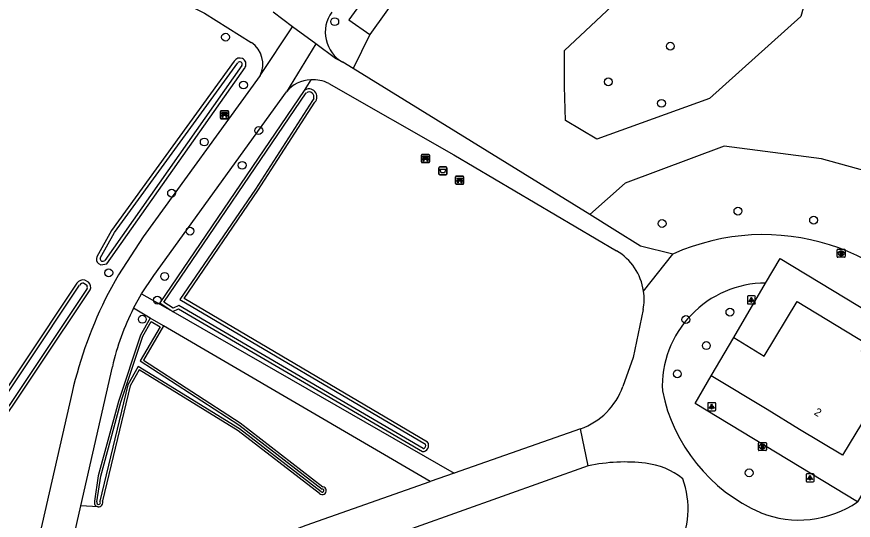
# Model space of a CAD drawing. Extents: x 157154 to 159278, y 385000 to 386650.
# Drawn here: x 158883.5 to 158988, y 385275.4 to 385338.3 of the extents above; entities that cross this region are included whole.
import ezdxf

# ---------------------------------------------------------------- set-up
doc = ezdxf.new("R2010")
doc.units = 0
for name, color, linetype in [('IMGEO_Afvalbak', 7, 'Continuous'), ('IMGEO_Bank', 7, 'Continuous'), ('IMGEO_Boom', 7, 'Continuous'), ('IMGEO_Gemengd_bos', 7, 'Continuous'), ('IMGEO_Grasland_overig', 7, 'Continuous'), ('IMGEO_Groenvoorziening', 7, 'Continuous'), ('IMGEO_Lichtpunt', 7, 'Continuous'), ('IMGEO_Pand', 7, 'Continuous'), ('IMGEO_Pand_nummerreeks', 7, 'Continuous'), ('IMGEO_Rioolput', 7, 'Continuous'), ('IMGEO_Voetpad_halfverhard', 7, 'Continuous'), ('IMGEO_Voetpad_onverhard', 7, 'Continuous'), ('IMGEO_Waterloop', 7, 'Continuous')]:
    doc.layers.add(name, color=color, linetype=linetype)

msp = doc.modelspace()

# ---------------------------------------------------------------- linework, layer by layer
at = {"layer": 'IMGEO_Afvalbak'}
for p, q in [((158936.23, 385318.65), (158936.23, 385319.45)), ((158936.23, 385319.45), (158936.23, 385318.65)), ((158936.33, 385319.55), (158937.12, 385319.55)), ((158937.12, 385319.55), (158936.33, 385319.55)), ((158937.22, 385319.45), (158937.22, 385318.65)), ((158937.22, 385318.65), (158937.22, 385319.45)), ((158937.12, 385318.55), (158936.33, 385318.55)), ((158936.33, 385318.55), (158937.12, 385318.55))]:
    msp.add_line(p, q, dxfattribs=at)
msp.add_lwpolyline([(158936.37, 385319.27), (158937.07, 385319.27), (158936.93, 385318.79), (158936.52, 385318.79), (158936.37, 385319.27)], dxfattribs=at)
for centre, start, end in [((158936.33, 385319.45), 90, 180), ((158936.33, 385319.45), 90, 180), ((158937.12, 385319.45), 0, 90), ((158937.12, 385319.45), 360, 90), ((158936.33, 385318.65), 180, 270), ((158936.33, 385318.65), 180, 270), ((158937.12, 385318.65), 270, 0), ((158937.12, 385318.65), 270, 0)]:
    msp.add_arc(centre, 0.1, start, end, dxfattribs=at)
at = {"layer": 'IMGEO_Bank'}
for p, q in [((158908.93, 385325.64), (158908.93, 385326.48)), ((158908.93, 385326.48), (158908.93, 385325.64)), ((158909.01, 385326.56), (158909.85, 385326.56)), ((158909.85, 385326.56), (158909.01, 385326.56)), ((158909.24, 385326.07), (158909.24, 385326.17)), ((158909.57, 385326.18), (158909.29, 385326.18)), ((158909.29, 385326.17), (158909.29, 385326.07)), ((158909.29, 385326.06), (158909.57, 385326.06)), ((158909.58, 385326.07), (158909.58, 385326.17)), ((158909.62, 385326.17), (158909.62, 385326.07)), ((158909.93, 385326.49), (158909.93, 385325.65)), ((158909.93, 385325.65), (158909.93, 385326.49)), ((158909.86, 385325.56), (158909.02, 385325.56)), ((158909.02, 385325.56), (158909.86, 385325.56)), ((158909.63, 385325.96), (158909.24, 385325.96)), ((158934.04, 385320.16), (158934.04, 385321.01)), ((158934.04, 385321.01), (158934.04, 385320.16)), ((158934.11, 385321.09), (158934.95, 385321.09)), ((158934.95, 385321.09), (158934.11, 385321.09)), ((158935.04, 385321.02), (158935.04, 385320.17)), ((158935.04, 385320.17), (158935.04, 385321.02)), ((158934.96, 385320.09), (158934.12, 385320.09)), ((158934.12, 385320.09), (158934.96, 385320.09)), ((158934.73, 385320.49), (158934.34, 385320.49)), ((158934.35, 385320.6), (158934.35, 385320.7)), ((158934.39, 385320.7), (158934.39, 385320.6)), ((158934.68, 385320.71), (158934.4, 385320.71)), ((158934.4, 385320.59), (158934.68, 385320.59)), ((158934.68, 385320.6), (158934.68, 385320.7)), ((158934.73, 385320.7), (158934.73, 385320.6)), ((158938.31, 385317.46), (158938.31, 385318.3)), ((158938.31, 385318.3), (158938.31, 385317.46)), ((158938.39, 385318.38), (158939.23, 385318.38)), ((158939.23, 385318.38), (158938.39, 385318.38)), ((158938.62, 385317.89), (158938.62, 385318)), ((158939.01, 385317.78), (158938.62, 385317.78)), ((158938.66, 385318), (158938.66, 385317.89)), ((158938.95, 385318), (158938.67, 385318)), ((158938.67, 385317.89), (158938.95, 385317.89)), ((158938.96, 385317.89), (158938.96, 385318)), ((158939, 385318), (158939, 385317.89)), ((158939.31, 385318.31), (158939.31, 385317.47)), ((158939.31, 385317.47), (158939.31, 385318.31)), ((158939.24, 385317.39), (158938.4, 385317.39)), ((158938.4, 385317.39), (158939.24, 385317.39))]:
    msp.add_line(p, q, dxfattribs=at)
for points in [[(158909.18, 385325.96), (158909.04, 385325.96), (158909.15, 385326.06), (158909.24, 385326.06)], [(158909.24, 385326.18), (158909.15, 385326.18), (158909.15, 385326.34), (158909.71, 385326.34), (158909.71, 385326.18), (158909.63, 385326.18)], [(158909.63, 385326.06), (158909.71, 385326.06), (158909.83, 385325.96), (158909.69, 385325.96)], [(158909.23, 385325.95), (158909.23, 385325.74), (158909.19, 385325.74), (158909.19, 385325.95)], [(158909.68, 385325.95), (158909.68, 385325.74), (158909.64, 385325.74), (158909.64, 385325.95)], [(158934.34, 385320.71), (158934.25, 385320.71), (158934.25, 385320.87), (158934.82, 385320.87), (158934.82, 385320.71), (158934.73, 385320.71)], [(158934.28, 385320.49), (158934.14, 385320.49), (158934.25, 385320.59), (158934.34, 385320.59)], [(158934.33, 385320.48), (158934.33, 385320.27), (158934.29, 385320.27), (158934.29, 385320.48)], [(158934.73, 385320.59), (158934.82, 385320.59), (158934.93, 385320.49), (158934.79, 385320.49)], [(158934.78, 385320.48), (158934.78, 385320.27), (158934.74, 385320.27), (158934.74, 385320.48)], [(158938.56, 385317.78), (158938.42, 385317.78), (158938.53, 385317.89), (158938.61, 385317.89)], [(158938.61, 385318), (158938.53, 385318), (158938.53, 385318.16), (158939.09, 385318.16), (158939.09, 385318), (158939.01, 385318)], [(158938.61, 385317.78), (158938.61, 385317.57), (158938.57, 385317.57), (158938.57, 385317.78)], [(158939.01, 385317.89), (158939.09, 385317.89), (158939.2, 385317.78), (158939.07, 385317.78)], [(158939.06, 385317.78), (158939.06, 385317.57), (158939.02, 385317.57), (158939.02, 385317.78)]]:
    msp.add_lwpolyline(points, dxfattribs=at)
for centre, radius, start, end in [((158909.01, 385326.48), 0.0779, 92.4484, 184.2845), ((158909.01, 385326.48), 0.0779, 92.4484, 184.2845), ((158909.24, 385326.17), 0.00671, 2.8957, 87.1043), ((158909.24, 385326.07), 0.00671, 272.8957, 357.1043), ((158909.29, 385326.17), 0.00671, 92.8957, 177.1043), ((158909.29, 385326.07), 0.00671, 182.8957, 267.1043), ((158909.57, 385326.17), 0.00671, 2.8957, 87.1043), ((158909.57, 385326.07), 0.00671, 272.8957, 357.1043), ((158909.63, 385326.17), 0.00671, 92.8957, 177.1043), ((158909.63, 385326.07), 0.00671, 182.8957, 267.1043), ((158909.85, 385326.48), 0.0779, 2.4484, 94.2845), ((158909.85, 385326.48), 0.0779, 2.4484, 94.2845), ((158909.01, 385325.64), 0.0779, 182.4484, 274.2845), ((158909.01, 385325.64), 0.0779, 182.4484, 274.2845), ((158909.18, 385325.95), 0.00671, 2.8957, 87.1043), ((158909.24, 385325.95), 0.00671, 92.8957, 177.1043), ((158909.63, 385325.95), 0.00671, 2.8957, 87.1043), ((158909.69, 385325.95), 0.00671, 92.8957, 177.1043), ((158909.85, 385325.64), 0.0779, 272.4484, 4.2845), ((158909.85, 385325.64), 0.0779, 272.4484, 4.2845), ((158934.11, 385321.01), 0.0779, 92.4484, 184.2845), ((158934.11, 385321.01), 0.0779, 92.4484, 184.2845), ((158934.96, 385321.01), 0.0779, 2.4484, 94.2845), ((158934.96, 385321.01), 0.0779, 2.4484, 94.2845), ((158934.11, 385320.17), 0.0779, 182.4484, 274.2845), ((158934.11, 385320.17), 0.0779, 182.4484, 274.2845), ((158934.28, 385320.48), 0.00671, 2.8957, 87.1043), ((158934.34, 385320.48), 0.00671, 92.8957, 177.1043), ((158934.34, 385320.7), 0.00671, 2.8957, 87.1043), ((158934.34, 385320.6), 0.00671, 272.8957, 357.1043), ((158934.4, 385320.7), 0.00671, 92.8957, 177.1043), ((158934.4, 385320.6), 0.00671, 182.8957, 267.1043), ((158934.68, 385320.7), 0.00671, 2.8957, 87.1043), ((158934.68, 385320.6), 0.00671, 272.8957, 357.1043), ((158934.73, 385320.7), 0.00671, 92.8957, 177.1043), ((158934.73, 385320.6), 0.00671, 182.8957, 267.1043), ((158934.73, 385320.48), 0.00671, 2.8957, 87.1043), ((158934.79, 385320.48), 0.00671, 92.8957, 177.1043), ((158934.96, 385320.17), 0.0779, 272.4484, 4.2845), ((158934.96, 385320.17), 0.0779, 272.4484, 4.2845), ((158938.39, 385318.31), 0.0779, 92.4484, 184.2845), ((158938.39, 385318.31), 0.0779, 92.4484, 184.2845), ((158938.56, 385317.78), 0.00671, 2.8957, 87.1043), ((158938.61, 385318), 0.00671, 2.8957, 87.1043), ((158938.61, 385317.89), 0.00671, 272.8957, 357.1043), ((158938.62, 385317.78), 0.00671, 92.8957, 177.1043), ((158938.67, 385318), 0.00671, 92.8957, 177.1043), ((158938.67, 385317.89), 0.00671, 182.8957, 267.1043), ((158938.95, 385318), 0.00671, 2.8957, 87.1043), ((158938.95, 385317.89), 0.00671, 272.8957, 357.1043), ((158939.01, 385318), 0.00671, 92.8957, 177.1043), ((158939.01, 385317.89), 0.00671, 182.8957, 267.1043), ((158939.01, 385317.78), 0.00671, 2.8957, 87.1043), ((158939.07, 385317.78), 0.00671, 92.8957, 177.1043), ((158939.23, 385318.31), 0.0779, 2.4484, 94.2845), ((158939.23, 385318.31), 0.0779, 2.4484, 94.2845), ((158938.39, 385317.46), 0.0779, 182.4484, 274.2845), ((158938.39, 385317.46), 0.0779, 182.4484, 274.2845), ((158939.23, 385317.46), 0.0779, 272.4484, 4.2845), ((158939.23, 385317.46), 0.0779, 272.4484, 4.2845)]:
    msp.add_arc(centre, radius, start, end, dxfattribs=at)
at = {"layer": 'IMGEO_Boom'}
for centre in [(158923.21, 385337.7), (158909.57, 385335.76), (158965.13, 385334.63), (158911.81, 385329.78), (158957.39, 385330.18), (158964.03, 385327.49), (158913.72, 385324.09), (158906.91, 385322.66), (158911.65, 385319.75), (158902.83, 385316.27), (158973.58, 385314.02), (158964.11, 385312.47), (158983.03, 385312.89), (158905.13, 385311.52), (158894.98, 385306.31), (158901.96, 385305.86), (158901.04, 385302.9), (158899.18, 385300.51), (158967.08, 385300.47), (158972.58, 385301.4), (158969.63, 385297.22), (158966.01, 385293.68), (158974.98, 385281.31)]:
    msp.add_circle(centre, 0.489, dxfattribs=at)
at = {"layer": 'IMGEO_Gemengd_bos'}
for points in [[(158910.66, 385332.76), (158895.31, 385311.6), (158893.47, 385308.32)], [(158893.7, 385307.47), (158893.98, 385307.32), (158894.74, 385307.43), (158912.03, 385331.99)], [(158920.21, 385330.44), (158919.39, 385329.08)], [(158934.8, 385285.16), (158904.38, 385303.09), (158913.61, 385316.58), (158920.73, 385327.63)], [(158892.46, 385305.15), (158892.01, 385305.41)], [(158891, 385305), (158877.2, 385284.35), (158872.07, 385275.9)], [(158873.01, 385274.81), (158892.67, 385304.19)], [(158902.99, 385301.47), (158903.71, 385301.8), (158934.16, 385283.97)], [(158902.99, 385301.47), (158938.12, 385281.28)], [(158901.81, 385299.67), (158899.33, 385295.41), (158911.39, 385287.56), (158921.73, 385279.58)], [(158935.13, 385280.23), (158901.81, 385299.67)], [(158921.32, 385278.72), (158911.14, 385286.57), (158898.77, 385294.19), (158897.67, 385292.19), (158894.2, 385277.83)], [(158893.64, 385277.08), (158891.49, 385277.2)]]:
    msp.add_lwpolyline(points, dxfattribs=at)
for centre, radius, start, end in [((158911.34, 385332.37), 0.785, 65.1242, 150.1059), ((158911.34, 385332.37), 0.784, 331.4126, 65.077), ((158920, 385328.3), 0.991, 317.4306, 127.7685), ((158894.24, 385308.07), 0.81, 161.9369, 227.7161), ((158891.79, 385304.5), 0.937, 76.4308, 147.1916), ((158891.79, 385304.49), 0.938, 340.9432, 44.1903), ((158934.19, 385284.72), 0.755, 268.2883, 35.3972), ((158921.66, 385279.09), 0.5, 227.2488, 81.9846), ((158893.69, 385277.62), 0.545, 264.4615, 22.0934)]:
    msp.add_arc(centre, radius, start, end, dxfattribs=at)
at = {"layer": 'IMGEO_Grasland_overig'}
for points in [[(158899.08, 385303.7), (158902.99, 385301.47)], [(158900.16, 385300.66), (158898.07, 385301.88)], [(158901.81, 385299.67), (158900.16, 385300.66)]]:
    msp.add_lwpolyline(points, dxfattribs=at)
at = {"layer": 'IMGEO_Groenvoorziening'}
for points in [[(158981.42, 385338.35), (158970.02, 385328.1), (158955.96, 385323.03), (158952.04, 385325.34), (158951.93, 385329.6), (158951.93, 385334.09), (158963.79, 385345.27), (158969.32, 385358.05), (158966.33, 385370.26), (158969.67, 385375.22), (158974.97, 385377.17), (158982, 385373.26), (158985.45, 385352.75), (158981.42, 385338.35)], [(158927.58, 385336.09), (158925.53, 385331.86)], [(158919.39, 385329.08), (158901.35, 385302.54), (158902.99, 385301.47)], [(159015.68, 385286.71), (159007.51, 385302.78), (159003.96, 385308.59), (158993.24, 385318.03), (158984.03, 385320.57), (158971.87, 385322.12), (158959.49, 385317.52), (158955.07, 385313.58)], [(158973.05, 385298.22), (158977.04, 385305.03)], [(158900.16, 385300.66), (158898.96, 385298.51), (158896.19, 385290.24), (158893.67, 385280.95), (158893.21, 385277.78)], [(158988.52, 385277.69), (158968.22, 385289.99), (158970.25, 385293.44)]]:
    msp.add_lwpolyline(points, dxfattribs=at)
msp.add_arc((158893.71, 385277.61), 0.533, 161.1695, 262.31, dxfattribs=at)
at = {"layer": 'IMGEO_Lichtpunt'}
for p, q in [((158974.76, 385303.32), (158974.76, 385302.51)), ((158974.76, 385303.32), (158974.76, 385302.51)), ((158975.66, 385303.42), (158974.85, 385303.42)), ((158975.66, 385303.42), (158974.85, 385303.42)), ((158975.75, 385302.51), (158975.75, 385303.32)), ((158975.75, 385302.51), (158975.75, 385303.32)), ((158974.85, 385302.42), (158975.66, 385302.42)), ((158974.85, 385302.42), (158975.66, 385302.42)), ((158969.81, 385289.98), (158969.81, 385289.18)), ((158969.81, 385289.98), (158969.81, 385289.18)), ((158970.71, 385290.08), (158969.9, 385290.08)), ((158970.71, 385290.08), (158969.9, 385290.08)), ((158970.8, 385289.18), (158970.8, 385289.98)), ((158970.8, 385289.18), (158970.8, 385289.98)), ((158969.9, 385289.08), (158970.71, 385289.08)), ((158969.9, 385289.08), (158970.71, 385289.08)), ((158982.99, 385281.19), (158982.18, 385281.19)), ((158982.99, 385281.19), (158982.18, 385281.19)), ((158982.09, 385281.1), (158982.09, 385280.29)), ((158982.09, 385281.1), (158982.09, 385280.29)), ((158982.18, 385280.19), (158982.99, 385280.19)), ((158982.18, 385280.19), (158982.99, 385280.19)), ((158983.09, 385280.29), (158983.09, 385281.1)), ((158983.09, 385280.29), (158983.09, 385281.1))]:
    msp.add_line(p, q, dxfattribs=at)
for points in [[(158975.13, 385302.98), (158975.17, 385302.96), (158974.98, 385302.69), (158974.94, 385302.72), (158975.13, 385302.98)], [(158975.23, 385302.94), (158975.28, 385302.94), (158975.28, 385302.61), (158975.23, 385302.61), (158975.23, 385302.94)], [(158975.34, 385302.96), (158975.38, 385302.98), (158975.57, 385302.72), (158975.53, 385302.69), (158975.34, 385302.96)], [(158970.18, 385289.65), (158970.22, 385289.62), (158970.03, 385289.36), (158969.99, 385289.38), (158970.18, 385289.65)], [(158970.28, 385289.6), (158970.33, 385289.6), (158970.33, 385289.28), (158970.28, 385289.28), (158970.28, 385289.6)], [(158970.39, 385289.62), (158970.43, 385289.65), (158970.62, 385289.38), (158970.58, 385289.36), (158970.39, 385289.62)], [(158982.46, 385280.76), (158982.5, 385280.73), (158982.31, 385280.47), (158982.28, 385280.5), (158982.46, 385280.76)], [(158982.56, 385280.71), (158982.61, 385280.71), (158982.61, 385280.39), (158982.56, 385280.39), (158982.56, 385280.71)], [(158982.67, 385280.73), (158982.71, 385280.76), (158982.9, 385280.5), (158982.86, 385280.47), (158982.67, 385280.73)]]:
    msp.add_lwpolyline(points, dxfattribs=at)
for centre in [(158975.26, 385303.12), (158970.31, 385289.78), (158982.59, 385280.89)]:
    msp.add_circle(centre, 0.0994, dxfattribs=at)
for centre, start, end in [((158974.85, 385303.32), 90, 180), ((158974.85, 385303.32), 90, 180), ((158975.66, 385303.32), 0, 90), ((158975.66, 385303.32), 0, 90), ((158974.85, 385302.51), 180, 270), ((158974.85, 385302.51), 180, 270), ((158975.66, 385302.51), 270, 0), ((158975.66, 385302.51), 270, 360), ((158969.9, 385289.98), 90, 180), ((158969.9, 385289.98), 90, 180), ((158970.71, 385289.98), 0, 90), ((158970.71, 385289.98), 0, 90), ((158969.9, 385289.18), 180, 270), ((158969.9, 385289.18), 180, 270), ((158970.71, 385289.18), 270, 0), ((158970.71, 385289.18), 270, 360), ((158982.18, 385281.1), 90, 180), ((158982.18, 385281.1), 90, 180), ((158982.99, 385281.1), 0, 90), ((158982.99, 385281.1), 0, 90), ((158982.18, 385280.29), 180, 270), ((158982.18, 385280.29), 180, 270), ((158982.99, 385280.29), 270, 0), ((158982.99, 385280.29), 270, 360)]:
    msp.add_arc(centre, 0.0946, start, end, dxfattribs=at)
at = {"layer": 'IMGEO_Pand'}
for points in [[(158973.05, 385298.22), (158976.86, 385295.91), (158980.99, 385302.72), (158989.54, 385297.54), (158988.97, 385296.6), (158993.07, 385294.12), (158986.64, 385283.51), (158981.29, 385286.74), (158977.23, 385289.21), (158970.25, 385293.44)], [(158970.25, 385293.44), (158973.05, 385298.22)]]:
    msp.add_lwpolyline(points, dxfattribs=at)
at = {"layer": 'IMGEO_Rioolput'}
for p, q in [((158985.98, 385308.33), (158985.98, 385309.18)), ((158986.05, 385309.25), (158986.9, 385309.25)), ((158986.49, 385308.47), (158986.46, 385308.47)), ((158986.47, 385309.03), (158986.49, 385309.03)), ((158986.98, 385309.18), (158986.98, 385308.33)), ((158986.9, 385308.25), (158986.05, 385308.25)), ((158976.13, 385284.17), (158976.13, 385285.02)), ((158976.21, 385285.1), (158977.06, 385285.1)), ((158976.62, 385284.88), (158976.65, 385284.88)), ((158976.64, 385284.32), (158976.62, 385284.32)), ((158977.13, 385285.02), (158977.13, 385284.17)), ((158977.06, 385284.1), (158976.21, 385284.1))]:
    msp.add_line(p, q, dxfattribs=at)
for points in [[(158985.98, 385308.33), (158985.98, 385309.18)], [(158986.05, 385309.25), (158986.9, 385309.25)], [(158986.57, 385308.95), (158986.31, 385308.95), (158986.31, 385308.55)], [(158986.31, 385308.55), (158986.44, 385308.55), (158986.44, 385308.72), (158986.45, 385308.72)], [(158986.49, 385308.87), (158986.44, 385308.87), (158986.44, 385308.79)], [(158986.44, 385308.79), (158986.49, 385308.79)], [(158986.5, 385308.69), (158986.57, 385308.55), (158986.71, 385308.55), (158986.64, 385308.68)], [(158986.98, 385309.18), (158986.98, 385308.33)], [(158986.9, 385308.25), (158986.05, 385308.25)], [(158976.13, 385284.17), (158976.13, 385285.02)], [(158976.21, 385285.1), (158977.06, 385285.1)], [(158976.72, 385284.8), (158976.47, 385284.8), (158976.47, 385284.4)], [(158976.47, 385284.4), (158976.59, 385284.4), (158976.59, 385284.56), (158976.61, 385284.56)], [(158976.65, 385284.72), (158976.59, 385284.72), (158976.59, 385284.64)], [(158976.59, 385284.64), (158976.65, 385284.64)], [(158976.65, 385284.53), (158976.72, 385284.4), (158976.86, 385284.4), (158976.8, 385284.52)], [(158977.13, 385285.02), (158977.13, 385284.17)], [(158977.06, 385284.1), (158976.21, 385284.1)]]:
    msp.add_lwpolyline(points, dxfattribs=at)
for centre, radius, start, end in [((158986.05, 385309.18), 0.0765, 91.552, 178.448), ((158986.05, 385309.18), 0.0765, 91.552, 178.448), ((158986.05, 385308.33), 0.0765, 181.552, 268.448), ((158986.05, 385308.33), 0.0765, 181.552, 268.448), ((158986.45, 385308.66), 0.0533, 26.0293, 88.6989), ((158986.5, 385308.78), 0.0964, 77.0061, 93.1865), ((158986.47, 385308.98), 0.19, 274.7715, 282.9687), ((158986.51, 385308.83), 0.0378, 276.6634, 79.6772), ((158986.57, 385308.84), 0.109, 350.3612, 89.416), ((158986.56, 385308.84), 0.112, 277.5842, 350.9817), ((158986.55, 385308.63), 0.108, 29.5134, 73.7905), ((158986.9, 385309.18), 0.0765, 1.552, 88.448), ((158986.9, 385309.18), 0.0765, 1.552, 88.448), ((158986.9, 385308.33), 0.0765, 271.552, 358.448), ((158986.9, 385308.33), 0.0765, 271.552, 358.448), ((158976.21, 385285.02), 0.0765, 91.552, 178.448), ((158976.21, 385285.02), 0.0765, 91.552, 178.448), ((158976.6, 385284.51), 0.0533, 26.0293, 88.6989), ((158976.65, 385284.62), 0.0964, 77.0061, 93.1865), ((158976.63, 385284.83), 0.19, 274.7715, 282.9687), ((158976.67, 385284.68), 0.0378, 276.6634, 79.6772), ((158976.72, 385284.69), 0.109, 350.3612, 89.416), ((158976.72, 385284.69), 0.112, 277.5842, 350.9817), ((158976.7, 385284.47), 0.108, 29.5134, 73.7905), ((158977.06, 385285.02), 0.0765, 1.552, 88.448), ((158977.06, 385285.02), 0.0765, 1.552, 88.448), ((158976.21, 385284.17), 0.0765, 181.552, 268.448), ((158976.21, 385284.17), 0.0765, 181.552, 268.448), ((158977.06, 385284.17), 0.0765, 271.552, 358.448), ((158977.06, 385284.17), 0.0765, 271.552, 358.448)]:
    msp.add_arc(centre, radius, start, end, dxfattribs=at)
for centre, major_axis, ratio, start_param, end_param in [((158986.46, 385308.75), (-0.387, 0.002), 0.722429, 4.712389, 7.853982), ((158986.49, 385308.75), (-0.39, 0.002), 0.717154, 1.570796, 4.712389), ((158976.62, 385284.6), (-0.387, 0.002), 0.722429, 4.712389, 7.853982), ((158976.64, 385284.6), (-0.39, 0.002), 0.717154, 1.570796, 4.712389)]:
    msp.add_ellipse(centre, major_axis=major_axis, ratio=ratio, start_param=start_param, end_param=end_param, dxfattribs=at)
at = {"layer": 'IMGEO_Voetpad_halfverhard'}
for points in [[(158882.86, 385351.03), (158906.93, 385338.75), (158912.79, 385335.08)], [(158917.95, 385337.07), (158915.52, 385338.87)], [(158913.9, 385330.95), (158917.95, 385337.07)], [(158920.85, 385334.93), (158917.95, 385337.07)], [(158920.85, 385334.93), (158917.17, 385328.94)], [(158924.21, 385332.62), (158923.31, 385333.11), (158920.85, 385334.93)], [(158925.53, 385331.86), (158924.21, 385332.62)], [(158955.07, 385313.58), (158925.53, 385331.86)], [(158913.9, 385330.95), (158899.26, 385310.8), (158896.19, 385306.08), (158894.91, 385303.73)], [(158922.46, 385329.98), (158938.1, 385321.05), (158958.41, 385309.07)], [(158899.08, 385303.7), (158900.59, 385305.99), (158917.17, 385328.94)], [(158965.46, 385308.66), (158961.42, 385309.66), (158958.2, 385311.65), (158955.07, 385313.58)], [(158961.79, 385304.03), (158965.46, 385308.66)], [(158977.04, 385305.03), (158978.84, 385308.11), (158993.5, 385299.22), (158992.43, 385297.45), (158998.32, 385293.88), (158988.52, 385277.69)], [(158898.07, 385301.88), (158899.08, 385303.7)], [(158961.74, 385301.72), (158960.48, 385295.72), (158959.21, 385292.11)], [(158891.49, 385277.2), (158895.43, 385294.58)], [(158890.4, 385291.39), (158884.1, 385263.88)], [(158953.92, 385286.82), (158938.12, 385281.28)], [(158954.89, 385282.17), (158953.92, 385286.82)], [(158954.89, 385282.17), (158890.39, 385259.19)], [(158938.12, 385281.28), (158935.13, 385280.23)], [(158890.05, 385263.4), (158919.62, 385274.79), (158935.13, 385280.23)], [(158888.68, 385264.85), (158891.49, 385277.2)]]:
    msp.add_lwpolyline(points, dxfattribs=at)
for centre, radius, start, end in [((158910.96, 385332.38), 3.27, 334.1848, 55.7938), ((158920.49, 385326.04), 4.41, 93.6933, 138.8923), ((158920.49, 385326.05), 4.39, 63.3141, 93.6952), ((158976.76, 385283.52), 27.56, 30.9177, 114.2082), ((158954.84, 385303.02), 7.02, 8.3106, 59.4732), ((158977.08, 385292.08), 12.95, 90.1654, 182.3453), ((158942.65, 385279.29), 53.63, 152.8798, 166.9619), ((158954.86, 385303.01), 7, 349.36, 8.3594), ((158925.84, 385287.69), 31.18, 152.9238, 167.2285), ((158951.02, 385295), 8.68, 289.5583, 340.5609), ((158984.93, 385295.78), 21.22, 191.4966, 246.234), ((158959.42, 385261.82), 20.85, 82.7773, 102.5405), ((158961.14, 385273.77), 8.78, 50.8946, 84.1029), ((158956.08, 385276.75), 11.27, 332.9654, 19.8748), ((158981.21, 385288.31), 12.89, 247.9815, 304.5175)]:
    msp.add_arc(centre, radius, start, end, dxfattribs=at)
at = {"layer": 'IMGEO_Voetpad_onverhard'}
msp.add_arc((158926.39, 385336.39), 4.36, 144.814, 239.9441, dxfattribs=at)
at = {"layer": 'IMGEO_Waterloop'}
for points in [[(158960.5, 385386.9), (158924.96, 385337.93), (158927.58, 385336.09)], [(158960.5, 385386.9), (158962.81, 385385.31), (158927.58, 385336.09)], [(158893.91, 385308.14), (158895.71, 385311.34), (158911.1, 385332.57)], [(158911.62, 385332.24), (158894.47, 385307.87)], [(158934.25, 385284.35), (158903.74, 385302.22), (158903.02, 385301.9), (158901.88, 385302.64), (158919.66, 385328.82)], [(158920.58, 385328.08), (158920.43, 385327.86), (158913.3, 385316.78), (158903.84, 385302.97), (158934.53, 385284.89)], [(158872.21, 385275.35), (158872.37, 385275.6), (158877.55, 385284.12), (158891.34, 385304.78)], [(158892.3, 385304.36), (158872.69, 385275.07)], [(158891.86, 385305.02), (158892.2, 385304.82)], [(158893.5, 385277.7), (158893.97, 385280.89), (158896.48, 385290.15), (158899.23, 385298.39), (158900.27, 385300.24), (158901.4, 385299.57), (158898.92, 385295.31), (158911.22, 385287.31), (158921.63, 385279.28)], [(158921.52, 385278.95), (158911.31, 385286.82), (158898.65, 385294.62), (158897.38, 385292.3), (158893.88, 385277.78)]]:
    msp.add_lwpolyline(points, dxfattribs=at)
for centre, radius, start, end in [((158911.34, 385332.37), 0.313, 335.3101, 139.0528), ((158920, 385328.3), 0.617, 339.5287, 122.9379), ((158894.22, 385308.07), 0.32, 166.3927, 321.2987), ((158891.79, 385304.5), 0.524, 81.7623, 147.4924), ((158891.78, 385304.49), 0.532, 346.189, 38.4444), ((158934.19, 385284.72), 0.38, 280.2256, 25.4577), ((158921.66, 385279.09), 0.198, 224.3234, 359.9771), ((158921.66, 385279.09), 0.197, 359.8709, 100.5664), ((158893.7, 385277.6), 0.224, 154.6117, 300.4989), ((158893.69, 385277.62), 0.243, 300.8531, 40.9299)]:
    msp.add_arc(centre, radius, start, end, dxfattribs=at)

# ---------------------------------------------------------------- texts
at = {"layer": 'IMGEO_Pand_nummerreeks'}
msp.add_text('2', height=1, rotation=328.791, dxfattribs=at).set_placement((158983, 385288.66))

doc.saveas('drawing.dxf')
